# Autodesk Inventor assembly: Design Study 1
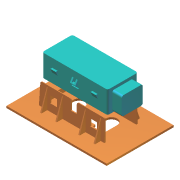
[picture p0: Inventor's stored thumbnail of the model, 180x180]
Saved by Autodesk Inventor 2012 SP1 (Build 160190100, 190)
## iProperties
Created: 2012-03
Part Number: Design Study 1
Document SubType Name: Assembly
Designer: dmm70056
Mass: 73.1431 g
Surface Area: 316.77 cm^2
Volume: 73.1431 cm^3
Density: 1 g/cm^3
Author: dmm70056
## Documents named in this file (3)
- D:\Backup\Autodesk CMU Course\Week 10 - Nonlinear Structural Analysis\Problem Set\Design Study 1.iam
- D:\Backup\Autodesk CMU Course\Week 10 - Nonlinear Structural Analysis\Problem Set\Design Study 1 - Side Shield.ipt
- D:\Backup\Autodesk CMU Course\Week 10 - Nonlinear Structural Analysis\Problem Set\Design Study 1 - Switch Box.ipt
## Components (2 placed, 2 different names)
1. Design Study 1 - Side Shield:1 — Mate:1, Mate:2, Mate:3
2. Design Study 1 - Switch Box:1 — Mate:1, Mate:2, Mate:3
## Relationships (3: Mate 3)
- Mate:1: Design Study 1 - Side Shield:1 ↔ Design Study 1 - Switch Box:1
- Mate:2: Design Study 1 - Side Shield:1 ↔ Design Study 1 - Switch Box:1
- Mate:3: Design Study 1 - Side Shield:1 ↔ Design Study 1 - Switch Box:1
